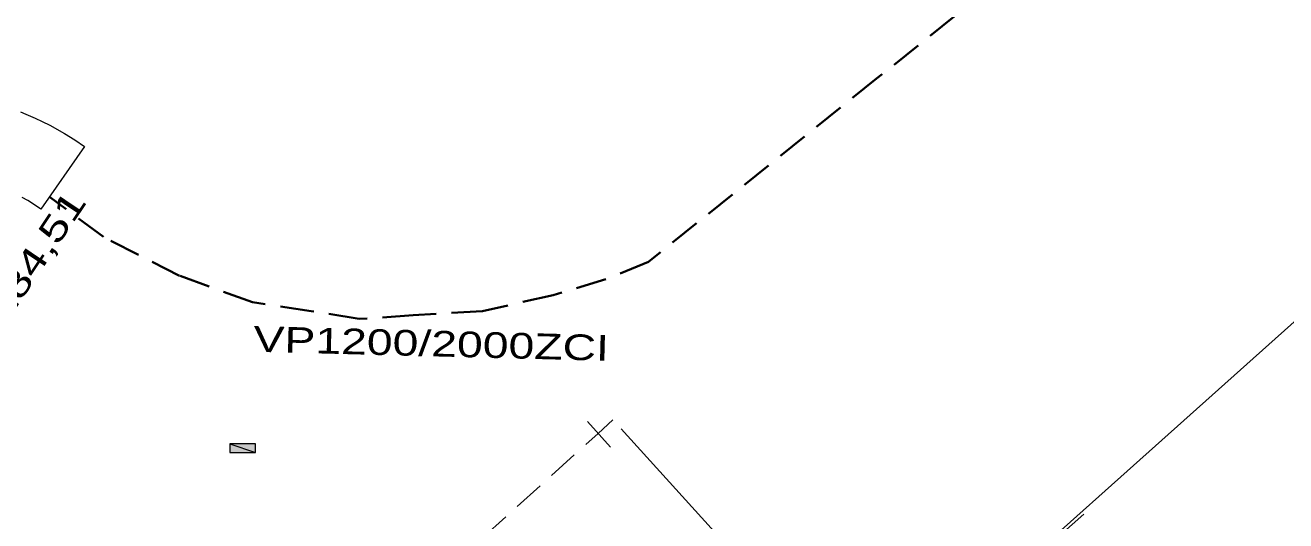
# Model space of a CAD drawing. Extents: x -740851 to -738888, y -1041382 to -1040235.
# Drawn here: x -739715.38 to -739666.27, y -1040548.46 to -1040529.17 of the extents above; entities that cross this region are included whole.
import ezdxf

# ---------------------------------------------------------------- set-up
doc = ezdxf.new("R2010")
doc.units = 0
doc.header["$LTSCALE"] = 0.4
doc.linetypes.add('MEDIUM_DASHED', pattern=[4.5, 3, -1.5])
for name, color, linetype, lineweight in [('18', 7, 'Continuous', 13), ('20', 7, 'MEDIUM_DASHED', 25), ('8', 7, 'Continuous', 13)]:
    doc.layers.add(name, color=color, linetype=linetype, lineweight=lineweight)

msp = doc.modelspace()

# ---------------------------------------------------------------- hatches: boundary and pattern name
at = {"layer": '18'}
msp.add_hatch(color=256, dxfattribs=at).paths.add_polyline_path([(-739707.41, -1040545.46), (-739707.41, -1040545.8), (-739706.41, -1040545.8), (-739706.41, -1040545.46)])

# ---------------------------------------------------------------- linework, layer by layer
msp.add_line((-739707.41, -1040545.46), (-739706.41, -1040545.8), dxfattribs=at)
at = {"layer": '18', "linetype": 'MEDIUM_DASHED', "lineweight": 40}
msp.add_lwpolyline([(-739642.96, -1040499.41), (-739676.38, -1040526.58), (-739682.21, -1040531.25), (-739691.095, -1040538.377), (-739692.756, -1040539.056), (-739694.818, -1040539.681), (-739697.571, -1040540.3), (-739700.262, -1040540.462), (-739702.366, -1040540.604), (-739704.248, -1040540.295), (-739706.53, -1040539.955), (-739709.371, -1040538.921), (-739712.34, -1040537.409), (-739714.435, -1040535.848)], dxfattribs=at)
at = {"layer": '18'}
msp.add_lwpolyline([(-739715.564, -1040532.545), (-739715.354, -1040532.631), (-739715.001, -1040532.785), (-739714.725, -1040532.915), (-739714.424, -1040533.067), (-739713.85, -1040533.386), (-739713.448, -1040533.633), (-739713.071, -1040533.886), (-739714.772, -1040536.333), (-739715.097, -1040536.116), (-739715.285, -1040535.999), (-739715.498, -1040535.875)], dxfattribs=at)
at = {"layer": '18', "lineweight": 25}
msp.add_lwpolyline([(-739659.45, -1040534.92), (-739688.27, -1040560.66), (-739696.73, -1040567.98)], dxfattribs=at)
at = {"layer": '18'}
msp.add_lwpolyline([(-739707.41, -1040545.46), (-739707.41, -1040545.8), (-739706.41, -1040545.8), (-739706.41, -1040545.46)], close=True, dxfattribs=at)
at = {"layer": '20'}
msp.add_lwpolyline([(-739674.14, -1040548.21), (-739688.774, -1040561.14), (-739702.73, -1040573.46)], dxfattribs=at)
at = {"layer": '8'}
msp.add_line((-739692.574, -1040545.6), (-739693.475, -1040544.6), dxfattribs=at)
at = {"layer": '8', "lineweight": 25}
for p, q in [((-739693.06, -1040545.06), (-739692.483, -1040544.536)), ((-739692.17, -1040544.88), (-739678.904, -1040559.46))]:
    msp.add_line(p, q, dxfattribs=at)
at = {"layer": '8', "linetype": 'MEDIUM_DASHED', "lineweight": 25}
msp.add_lwpolyline([(-739709.965, -1040560.292), (-739709.59, -1040559.954), (-739693.06, -1040545.06)], dxfattribs=at)

# ---------------------------------------------------------------- texts
at = {"layer": '18'}
for s, rotation, width, p in [('184,51', 56.105, 1.4, (-739716.153, -1040540.811)), ('VP1200/2000ZCI', 358.531, 1.35, (-739706.499, -1040541.881))]:
    msp.add_text(s, height=1, rotation=rotation, dxfattribs=dict(at, width=width)).set_placement(p)

doc.saveas('drawing.dxf')
